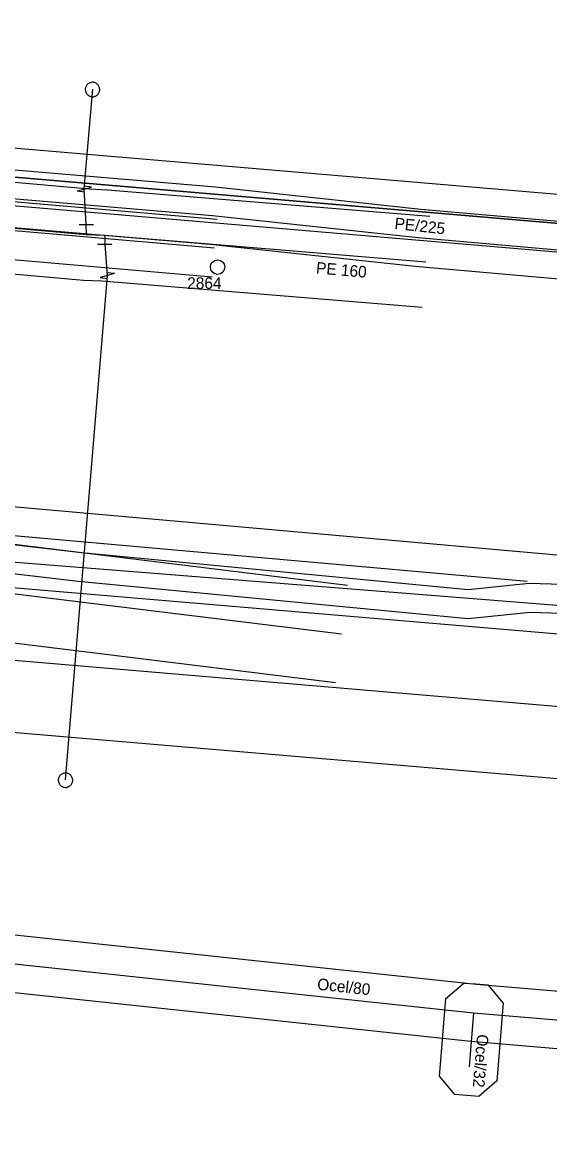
# Model space of a CAD drawing. Extents: x -762993 to -761845, y -975230 to -974501.
# Drawn here: x -762178.08 to -762159.81, y -975032.89 to -974994.1 of the extents above; entities that cross this region are included whole.
import ezdxf

# ---------------------------------------------------------------- set-up
doc = ezdxf.new("R2010")
doc.units = 0
for name, color, linetype in [('IS_CETIN_OP', 7, 'Continuous'), ('IS_CETIN_podzem metalika zam', 7, 'Continuous'), ('IS_CETIN_podzem optika zam', 7, 'Continuous'), ('IS_CETIN_podzem out of order', 7, 'Continuous'), ('IS_CEZ-T_parovod', 7, 'Continuous'), ('IS_CEZ-T_parovod OP', 7, 'Continuous'), ('IS_CRA_podzem telekomunikace', 7, 'Continuous'), ('IS_DPmUL_OP', 7, 'Continuous'), ('IS_DPmUL_trakce anotace', 7, 'Continuous'), ('IS_DPmUL_trakce stozary', 7, 'Continuous'), ('IS_DPmUL_VO vedeni podzem', 7, 'Continuous'), ('IS_GASNET_plyn NTL anotace', 7, 'Continuous'), ('IS_GASNET_plyn NTL pripojky', 7, 'Continuous'), ('IS_GASNET_plyn NTL rad', 7, 'Continuous'), ('IS_GASNET_plyn OP', 7, 'Continuous'), ('IS_SCVK_kanalizace jednotna', 7, 'Continuous'), ('IS_SCVK_kanalizace OP', 7, 'Continuous'), ('IS_SCVK_vodovod anotace', 7, 'Continuous'), ('IS_SCVK_vodovod OP', 7, 'Continuous'), ('IS_SCVK_vodovod pripojky', 7, 'Continuous'), ('IS_SCVK_vodovod privadec', 7, 'Continuous'), ('IS_SCVK_vodovod znaky', 7, 'Continuous')]:
    doc.layers.add(name, color=color, linetype=linetype)

msp = doc.modelspace()

# ---------------------------------------------------------------- linework, layer by layer
at = {"layer": 'IS_CETIN_OP'}
msp.add_line((-762187.135, -975010.105), (-762159.034, -975012.594), dxfattribs=at)
for points in [[(-762217.822, -974995.035), (-762216.005, -974995.184), (-762184.57, -974998.003), (-762178.542, -974998.433), (-762152.471, -975000.654), (-762131.203, -975002.624), (-762124.809, -975003.153), (-762118.93, -975003.623), (-762113.193, -975004.083), (-762107.364, -975004.514), (-762100.398, -975005.204), (-762087.589, -975006.295)], [(-762217.984, -974997.029), (-762216.175, -974997.176), (-762184.73, -974999.997), (-762178.698, -975000.427), (-762152.649, -975002.646), (-762131.377, -975004.616), (-762124.971, -975005.147), (-762119.09, -975005.617), (-762113.347, -975006.077), (-762107.536, -975006.506), (-762100.582, -975007.196), (-762087.759, -975008.287)], [(-762105.752, -975019.119), (-762108.956, -975019.272), (-762116.886, -975018.639), (-762118.209, -975018.27), (-762121.344, -975018.26), (-762126.32, -975017.734), (-762130.385, -975017.267), (-762131.367, -975016.856), (-762135.732, -975016.981), (-762156.063, -975015.079), (-762157.972, -975014.627), (-762160.485, -975014.551), (-762162.638, -975014.765), (-762176.145, -975013.475), (-762180.887, -975012.925), (-762183.621, -975012.711), (-762185.704, -975012.236), (-762187.743, -975012.352), (-762193.286, -975011.893), (-762194.38, -975011.419), (-762195.086, -975011.619)]]:
    msp.add_lwpolyline(points, dxfattribs=at)
at = {"layer": 'IS_CETIN_podzem metalika zam'}
msp.add_lwpolyline([(-762105.8, -975018.12), (-762108.94, -975018.27), (-762116.71, -975017.65), (-762118.07, -975017.27), (-762121.29, -975017.26), (-762126.21, -975016.74), (-762130.13, -975016.29), (-762131.18, -975015.85), (-762135.7, -975015.98), (-762155.9, -975014.09), (-762157.84, -975013.63), (-762160.52, -975013.55), (-762162.64, -975013.76), (-762176.04, -975012.48), (-762180.79, -975011.93), (-762183.47, -975011.72), (-762185.62, -975011.23), (-762187.73, -975011.35), (-762193.04, -975010.91), (-762194.31, -975010.36), (-762195.97, -975010.83)], dxfattribs=at)
at = {"layer": 'IS_CETIN_podzem optika zam'}
for points in [[(-762217.903, -974996.032), (-762216.09, -974996.18), (-762184.65, -974999), (-762178.62, -974999.43), (-762152.56, -975001.65), (-762131.29, -975003.62), (-762124.89, -975004.15), (-762119.01, -975004.62), (-762113.27, -975005.08), (-762107.45, -975005.51), (-762100.49, -975006.2), (-762087.674, -975007.291)], [(-762187.23, -975011.1), (-762160.59, -975013.46)]]:
    msp.add_lwpolyline(points, dxfattribs=at)
at = {"layer": 'IS_CETIN_podzem out of order'}
msp.add_lwpolyline([(-762250.2, -975005.66), (-762210.15, -975010), (-762201.16, -975010.99), (-762121.16, -975017.35), (-762071.23, -975020.85), (-762043.47, -975023.41)], dxfattribs=at)
at = {"layer": 'IS_CEZ-T_parovod'}
msp.add_lwpolyline([(-761997.94, -975128.34), (-762040.63, -975080.79), (-762092.91, -975023.16), (-762093.78, -975023), (-762095.1, -975022.88), (-762139.5, -975019.26), (-762139.25, -975015.36), (-762142, -975015.09), (-762142.45, -975019.26), (-762189.8, -975015.24), (-762189.54, -975011.07), (-762194.02, -975010.75), (-762194.39, -975014.25), (-762239.28, -975010.18), (-762239.14, -975006.45), (-762242.94, -975006.24), (-762243.22, -975009.53), (-762252.6, -975008.69), (-762274.12, -975007.08), (-762277.86, -975004.82)], dxfattribs=at)
at = {"layer": 'IS_CEZ-T_parovod OP'}
for points in [[(-761996.08, -975126.67), (-762038.774, -975079.115), (-762091.626, -975020.854), (-762093.44, -975020.521), (-762094.885, -975020.389), (-762136.848, -975016.968), (-762136.601, -975013.108), (-762144.22, -975012.36), (-762144.673, -975016.562), (-762187.153, -975012.956), (-762186.891, -975008.753), (-762196.252, -975008.084), (-762196.617, -975011.538), (-762236.693, -975007.904), (-762236.55, -975004.089), (-762245.225, -975003.61), (-762245.498, -975006.816), (-762252.395, -975006.198), (-762273.338, -975004.632), (-762275.663, -975003.227)], [(-761999.8, -975130.01), (-762042.486, -975082.465), (-762094.187, -975025.473), (-762095.315, -975025.371), (-762140.2, -975021.711), (-762140.227, -975021.958), (-762192.447, -975017.524), (-762192.411, -975016.94), (-762241.867, -975012.456), (-762241.856, -975012.162), (-762252.805, -975011.182), (-762274.902, -975009.528), (-762278.275, -975007.49)]]:
    msp.add_lwpolyline(points, dxfattribs=at)
at = {"layer": 'IS_CRA_podzem telekomunikace'}
msp.add_lwpolyline([(-762257.583, -974994.102), (-762251.601, -974995.42), (-762242.483, -974996.496), (-762240.634, -974996.224), (-762237.225, -974994.464), (-762216.085, -974996.188), (-762184.646, -974998.998), (-762178.626, -974999.438), (-762152.565, -975001.658), (-762131.295, -975003.618), (-762124.896, -975004.158), (-762119.016, -975004.628), (-762113.267, -975005.088), (-762107.455, -975005.508), (-762100.504, -975006.198), (-762086.855, -975007.364)], dxfattribs=at)
at = {"layer": 'IS_DPmUL_OP'}
msp.add_line((-762171.511, -975002.926), (-762197.933, -975000.64), dxfattribs=at)
msp.add_lwpolyline([(-762171.339, -975000.934), (-762197.755, -974998.648)], dxfattribs=at)
at = {"layer": 'IS_DPmUL_trakce stozary'}
msp.add_circle((-762171.318, -975002.583), 0.25, dxfattribs=at)
at = {"layer": 'IS_DPmUL_VO vedeni podzem'}
msp.add_lwpolyline([(-762171.425, -975001.93), (-762197.841, -974999.644)], dxfattribs=at)
at = {"layer": 'IS_GASNET_plyn NTL pripojky'}
msp.add_lwpolyline([(-762162.45, -975028.42), (-762162.6, -975030.29)], dxfattribs=at)
at = {"layer": 'IS_GASNET_plyn NTL rad'}
for points in [[(-762152.06, -975002.65), (-762164.37, -975001.57), (-762171.49, -975000.8), (-762180.35, -975000.05), (-762191.928, -974999.15), (-762192.87, -974999.06), (-762193.62, -974998.98), (-762196.019, -974998.86), (-762209.34, -974997.53), (-762211.92, -974997.29), (-762211.926, -974997.289), (-762215.99, -974996.98), (-762229.04, -974995.92), (-762230.6, -974995.81), (-762231.15, -974995.79), (-762234.191, -974995.47), (-762234.57, -974995.47)], [(-762200.13, -975024.62), (-762197.953, -975024.87), (-762195.07, -975025.2), (-762193.3, -975025.13), (-762162.45, -975028.42), (-762149.72, -975029.5), (-762136.08, -975030.63)]]:
    msp.add_lwpolyline(points, dxfattribs=at)
at = {"layer": 'IS_GASNET_plyn OP'}
for points in [[(-762215.912, -974995.983), (-762211.806, -974996.295), (-762211.795, -974996.297), (-762209.244, -974996.535), (-762195.944, -974997.862), (-762193.542, -974997.983), (-762192.769, -974998.065), (-762191.842, -974998.154), (-762180.269, -974999.053), (-762171.394, -974999.805), (-762164.273, -975000.575), (-762151.966, -975001.654)], [(-762152.154, -975003.646), (-762164.467, -975002.565), (-762171.586, -975001.795), (-762180.431, -975001.047), (-762192.014, -975000.146), (-762192.971, -975000.055), (-762193.698, -974999.977), (-762196.094, -974999.858), (-762209.436, -974998.525), (-762212.002, -974998.286), (-762212.024, -974998.284), (-762212.049, -974998.282), (-762216.068, -974997.977)]]:
    msp.add_lwpolyline(points, dxfattribs=at)
for points in [[(-762200.428, -975023.58), (-762200.016, -975023.627), (-762195.033, -975024.198), (-762193.267, -975024.128), (-762162.355, -975027.424), (-762149.636, -975028.503), (-762135.997, -975029.633), (-762135.584, -975029.667), (-762135.049, -975030.3), (-762135.083, -975030.713), (-762135.117, -975031.126), (-762135.75, -975031.661), (-762136.163, -975031.627), (-762149.804, -975030.497), (-762162.545, -975029.416), (-762193.333, -975026.132), (-762195.107, -975026.202), (-762200.244, -975025.613), (-762200.655, -975025.566), (-762201.17, -975024.918), (-762201.123, -975024.506), (-762201.076, -975024.095)], [(-762161.42, -975028.087), (-762161.453, -975028.5), (-762161.603, -975030.37), (-762161.636, -975030.783), (-762162.267, -975031.32), (-762162.68, -975031.287), (-762163.093, -975031.254), (-762163.63, -975030.623), (-762163.597, -975030.21), (-762163.447, -975028.34), (-762163.414, -975027.927), (-762162.783, -975027.39), (-762162.37, -975027.423), (-762161.957, -975027.456)]]:
    msp.add_lwpolyline(points, close=True, dxfattribs=at)
at = {"layer": 'IS_SCVK_kanalizace jednotna'}
msp.add_lwpolyline([(-762195.393, -975011.808), (-762167.023, -975015.287)], dxfattribs=at)
at = {"layer": 'IS_SCVK_kanalizace OP'}
for p, q in [((-762195.236, -975010.115), (-762166.816, -975013.6)), ((-762195.55, -975013.501), (-762167.23, -975016.974))]:
    msp.add_line(p, q, dxfattribs=at)
at = {"layer": 'IS_SCVK_vodovod OP'}
for points in [[(-762202.898, -974997.152), (-762199.388, -974997.773), (-762175.758, -974999.875), (-762175.129, -974999.903), (-762163.968, -975000.821)], [(-762201.291, -975000.645), (-762199.804, -975000.909), (-762175.968, -975003.029), (-762175.329, -975003.057), (-762164.228, -975003.971)]]:
    msp.add_lwpolyline(points, dxfattribs=at)
at = {"layer": 'IS_SCVK_vodovod pripojky'}
for points in [[(-762175.939, -974999.873), (-762175.642, -974996.418)], [(-762175.87, -975001.106), (-762175.939, -974999.873)], [(-762175.228, -975001.8), (-762175.141, -975002.876)], [(-762175.141, -975002.876), (-762176.6, -975020.349)]]:
    msp.add_lwpolyline(points, dxfattribs=at)
at = {"layer": 'IS_SCVK_vodovod privadec'}
msp.add_lwpolyline([(-762202.357, -974998.852), (-762199.596, -974999.341), (-762175.863, -975001.452), (-762175.229, -975001.48), (-762164.098, -975002.396)], dxfattribs=at)
at = {"layer": 'IS_SCVK_vodovod znaky'}
for points in [[(-762175.904, -974996.409), (-762175.905, -974996.435)], [(-762175.904, -974996.409), (-762175.905, -974996.435)], [(-762175.905, -974996.435), (-762175.902, -974996.461)], [(-762175.905, -974996.435), (-762175.902, -974996.461)], [(-762175.9, -974996.383), (-762175.904, -974996.409)], [(-762175.9, -974996.383), (-762175.904, -974996.409)], [(-762175.902, -974996.461), (-762175.898, -974996.487)], [(-762175.902, -974996.461), (-762175.898, -974996.487)], [(-762175.894, -974996.357), (-762175.9, -974996.383)], [(-762175.894, -974996.357), (-762175.9, -974996.383)], [(-762175.898, -974996.487), (-762175.89, -974996.512)], [(-762175.898, -974996.487), (-762175.89, -974996.512)], [(-762175.885, -974996.333), (-762175.894, -974996.357)], [(-762175.885, -974996.333), (-762175.894, -974996.357)], [(-762175.89, -974996.512), (-762175.88, -974996.535)], [(-762175.89, -974996.512), (-762175.88, -974996.535)], [(-762175.874, -974996.309), (-762175.885, -974996.333)], [(-762175.874, -974996.309), (-762175.885, -974996.333)], [(-762175.861, -974996.287), (-762175.874, -974996.309)], [(-762175.861, -974996.287), (-762175.874, -974996.309)], [(-762175.845, -974996.266), (-762175.861, -974996.287)], [(-762175.845, -974996.266), (-762175.861, -974996.287)], [(-762175.827, -974996.247), (-762175.845, -974996.266)], [(-762175.827, -974996.247), (-762175.845, -974996.266)], [(-762175.807, -974996.23), (-762175.827, -974996.247)], [(-762175.807, -974996.23), (-762175.827, -974996.247)], [(-762175.785, -974996.216), (-762175.807, -974996.23)], [(-762175.785, -974996.216), (-762175.807, -974996.23)], [(-762175.762, -974996.202), (-762175.785, -974996.216)], [(-762175.762, -974996.202), (-762175.785, -974996.216)], [(-762175.738, -974996.192), (-762175.762, -974996.202)], [(-762175.738, -974996.192), (-762175.762, -974996.202)], [(-762175.713, -974996.185), (-762175.738, -974996.192)], [(-762175.713, -974996.185), (-762175.738, -974996.192)], [(-762175.687, -974996.18), (-762175.713, -974996.185)], [(-762175.687, -974996.18), (-762175.713, -974996.185)], [(-762175.662, -974996.179), (-762175.687, -974996.18)], [(-762175.662, -974996.179), (-762175.687, -974996.18)], [(-762175.635, -974996.179), (-762175.662, -974996.179)], [(-762175.635, -974996.179), (-762175.662, -974996.179)], [(-762175.609, -974996.182), (-762175.635, -974996.179)], [(-762175.609, -974996.182), (-762175.635, -974996.179)], [(-762175.584, -974996.189), (-762175.609, -974996.182)], [(-762175.584, -974996.189), (-762175.609, -974996.182)], [(-762175.559, -974996.197), (-762175.584, -974996.189)], [(-762175.559, -974996.197), (-762175.584, -974996.189)], [(-762175.535, -974996.208), (-762175.559, -974996.197)], [(-762175.535, -974996.208), (-762175.559, -974996.197)], [(-762175.513, -974996.223), (-762175.535, -974996.208)], [(-762175.513, -974996.223), (-762175.535, -974996.208)], [(-762175.492, -974996.238), (-762175.513, -974996.223)], [(-762175.492, -974996.238), (-762175.513, -974996.223)], [(-762175.473, -974996.257), (-762175.492, -974996.238)], [(-762175.473, -974996.257), (-762175.492, -974996.238)], [(-762175.457, -974996.276), (-762175.473, -974996.257)], [(-762175.457, -974996.276), (-762175.473, -974996.257)], [(-762175.442, -974996.298), (-762175.457, -974996.276)], [(-762175.442, -974996.298), (-762175.457, -974996.276)], [(-762175.429, -974996.321), (-762175.442, -974996.298)], [(-762175.429, -974996.321), (-762175.442, -974996.298)], [(-762175.435, -974996.547), (-762175.424, -974996.524)], [(-762175.435, -974996.547), (-762175.424, -974996.524)], [(-762175.419, -974996.345), (-762175.429, -974996.321)], [(-762175.419, -974996.345), (-762175.429, -974996.321)], [(-762175.424, -974996.524), (-762175.415, -974996.499)], [(-762175.424, -974996.524), (-762175.415, -974996.499)], [(-762175.412, -974996.37), (-762175.419, -974996.345)], [(-762175.412, -974996.37), (-762175.419, -974996.345)], [(-762175.415, -974996.499), (-762175.409, -974996.474)], [(-762175.415, -974996.499), (-762175.409, -974996.474)], [(-762175.407, -974996.395), (-762175.412, -974996.37)], [(-762175.407, -974996.395), (-762175.412, -974996.37)], [(-762175.409, -974996.474), (-762175.405, -974996.448)], [(-762175.409, -974996.474), (-762175.405, -974996.448)], [(-762175.404, -974996.422), (-762175.407, -974996.395)], [(-762175.404, -974996.422), (-762175.407, -974996.395)], [(-762175.405, -974996.448), (-762175.404, -974996.422)], [(-762175.405, -974996.448), (-762175.404, -974996.422)], [(-762175.88, -974996.535), (-762175.868, -974996.559)], [(-762175.88, -974996.535), (-762175.868, -974996.559)], [(-762175.868, -974996.559), (-762175.853, -974996.58)], [(-762175.868, -974996.559), (-762175.853, -974996.58)], [(-762175.853, -974996.58), (-762175.836, -974996.601)], [(-762175.853, -974996.58), (-762175.836, -974996.601)], [(-762175.836, -974996.601), (-762175.817, -974996.618)], [(-762175.836, -974996.601), (-762175.817, -974996.618)], [(-762175.817, -974996.618), (-762175.797, -974996.634)], [(-762175.817, -974996.618), (-762175.797, -974996.634)], [(-762175.797, -974996.634), (-762175.774, -974996.648)], [(-762175.797, -974996.634), (-762175.774, -974996.648)], [(-762175.774, -974996.648), (-762175.751, -974996.659)], [(-762175.774, -974996.648), (-762175.751, -974996.659)], [(-762175.751, -974996.659), (-762175.725, -974996.668)], [(-762175.751, -974996.659), (-762175.725, -974996.668)], [(-762175.725, -974996.668), (-762175.7, -974996.674)], [(-762175.725, -974996.668), (-762175.7, -974996.674)], [(-762175.7, -974996.674), (-762175.674, -974996.677)], [(-762175.7, -974996.674), (-762175.674, -974996.677)], [(-762175.674, -974996.677), (-762175.648, -974996.677)], [(-762175.674, -974996.677), (-762175.648, -974996.677)], [(-762175.648, -974996.677), (-762175.622, -974996.676)], [(-762175.648, -974996.677), (-762175.622, -974996.676)], [(-762175.622, -974996.676), (-762175.596, -974996.671)], [(-762175.622, -974996.676), (-762175.596, -974996.671)], [(-762175.596, -974996.671), (-762175.571, -974996.664)], [(-762175.596, -974996.671), (-762175.571, -974996.664)], [(-762175.571, -974996.664), (-762175.547, -974996.654)], [(-762175.571, -974996.664), (-762175.547, -974996.654)], [(-762175.547, -974996.654), (-762175.524, -974996.642)], [(-762175.547, -974996.654), (-762175.524, -974996.642)], [(-762175.524, -974996.642), (-762175.503, -974996.626)], [(-762175.524, -974996.642), (-762175.503, -974996.626)], [(-762175.503, -974996.626), (-762175.483, -974996.61)], [(-762175.503, -974996.626), (-762175.483, -974996.61)], [(-762175.483, -974996.61), (-762175.465, -974996.591)], [(-762175.483, -974996.61), (-762175.465, -974996.591)], [(-762175.465, -974996.591), (-762175.448, -974996.57)], [(-762175.465, -974996.591), (-762175.448, -974996.57)], [(-762175.448, -974996.57), (-762175.435, -974996.547)], [(-762175.448, -974996.57), (-762175.435, -974996.547)], [(-762176.186, -974999.936), (-762175.692, -974999.81)], [(-762176.186, -974999.936), (-762175.933, -974999.973)], [(-762175.692, -974999.81), (-762175.944, -974999.773)], [(-762176.12, -975001.111), (-762175.62, -975001.101)], [(-762175.863, -975001.452), (-762175.87, -975001.106)], [(-762175.229, -975001.48), (-762175.228, -975001.8)], [(-762174.978, -975001.798), (-762175.478, -975001.801)], [(-762174.895, -975002.807), (-762175.386, -975002.945)], [(-762175.386, -975002.945), (-762175.133, -975002.976)], [(-762174.895, -975002.807), (-762175.149, -975002.775)], [(-762176.763, -975020.182), (-762176.781, -975020.201)], [(-762176.763, -975020.182), (-762176.781, -975020.201)], [(-762176.743, -975020.165), (-762176.763, -975020.182)], [(-762176.743, -975020.165), (-762176.763, -975020.182)], [(-762176.722, -975020.15), (-762176.743, -975020.165)], [(-762176.722, -975020.15), (-762176.743, -975020.165)], [(-762176.699, -975020.137), (-762176.722, -975020.15)], [(-762176.699, -975020.137), (-762176.722, -975020.15)], [(-762176.675, -975020.127), (-762176.699, -975020.137)], [(-762176.675, -975020.127), (-762176.699, -975020.137)], [(-762176.65, -975020.119), (-762176.675, -975020.127)], [(-762176.65, -975020.119), (-762176.675, -975020.127)], [(-762176.625, -975020.114), (-762176.65, -975020.119)], [(-762176.625, -975020.114), (-762176.65, -975020.119)], [(-762176.599, -975020.111), (-762176.625, -975020.114)], [(-762176.599, -975020.111), (-762176.625, -975020.114)], [(-762176.572, -975020.111), (-762176.599, -975020.111)], [(-762176.572, -975020.111), (-762176.599, -975020.111)], [(-762176.546, -975020.116), (-762176.572, -975020.111)], [(-762176.546, -975020.116), (-762176.572, -975020.111)], [(-762176.521, -975020.122), (-762176.546, -975020.116)], [(-762176.521, -975020.122), (-762176.546, -975020.116)], [(-762176.496, -975020.13), (-762176.521, -975020.122)], [(-762176.496, -975020.13), (-762176.521, -975020.122)], [(-762176.473, -975020.141), (-762176.496, -975020.13)], [(-762176.473, -975020.141), (-762176.496, -975020.13)], [(-762176.45, -975020.154), (-762176.473, -975020.141)], [(-762176.45, -975020.154), (-762176.473, -975020.141)], [(-762176.429, -975020.17), (-762176.45, -975020.154)], [(-762176.429, -975020.17), (-762176.45, -975020.154)], [(-762176.41, -975020.188), (-762176.429, -975020.17)], [(-762176.41, -975020.188), (-762176.429, -975020.17)], [(-762176.836, -975020.318), (-762176.839, -975020.344)], [(-762176.836, -975020.318), (-762176.839, -975020.344)], [(-762176.839, -975020.344), (-762176.839, -975020.371)], [(-762176.839, -975020.344), (-762176.839, -975020.371)], [(-762176.839, -975020.371), (-762176.837, -975020.396)], [(-762176.839, -975020.371), (-762176.837, -975020.396)], [(-762176.837, -975020.396), (-762176.832, -975020.423)], [(-762176.837, -975020.396), (-762176.832, -975020.423)], [(-762176.83, -975020.293), (-762176.836, -975020.318)], [(-762176.83, -975020.293), (-762176.836, -975020.318)], [(-762176.832, -975020.423), (-762176.824, -975020.447)], [(-762176.832, -975020.423), (-762176.824, -975020.447)], [(-762176.822, -975020.269), (-762176.83, -975020.293)], [(-762176.822, -975020.269), (-762176.83, -975020.293)], [(-762176.824, -975020.447), (-762176.814, -975020.471)], [(-762176.824, -975020.447), (-762176.814, -975020.471)], [(-762176.811, -975020.244), (-762176.822, -975020.269)], [(-762176.811, -975020.244), (-762176.822, -975020.269)], [(-762176.814, -975020.471), (-762176.801, -975020.494)], [(-762176.814, -975020.471), (-762176.801, -975020.494)], [(-762176.797, -975020.222), (-762176.811, -975020.244)], [(-762176.797, -975020.222), (-762176.811, -975020.244)], [(-762176.801, -975020.494), (-762176.786, -975020.516)], [(-762176.801, -975020.494), (-762176.786, -975020.516)], [(-762176.781, -975020.201), (-762176.797, -975020.222)], [(-762176.781, -975020.201), (-762176.797, -975020.222)], [(-762176.786, -975020.516), (-762176.769, -975020.535)], [(-762176.786, -975020.516), (-762176.769, -975020.535)], [(-762176.769, -975020.535), (-762176.75, -975020.554)], [(-762176.769, -975020.535), (-762176.75, -975020.554)], [(-762176.75, -975020.554), (-762176.729, -975020.569)], [(-762176.75, -975020.554), (-762176.729, -975020.569)], [(-762176.729, -975020.569), (-762176.706, -975020.582)], [(-762176.729, -975020.569), (-762176.706, -975020.582)], [(-762176.48, -975020.586), (-762176.457, -975020.573)], [(-762176.48, -975020.586), (-762176.457, -975020.573)], [(-762176.457, -975020.573), (-762176.435, -975020.558)], [(-762176.457, -975020.573), (-762176.435, -975020.558)], [(-762176.435, -975020.558), (-762176.415, -975020.541)], [(-762176.435, -975020.558), (-762176.415, -975020.541)], [(-762176.415, -975020.541), (-762176.398, -975020.522)], [(-762176.415, -975020.541), (-762176.398, -975020.522)], [(-762176.393, -975020.208), (-762176.41, -975020.188)], [(-762176.393, -975020.208), (-762176.41, -975020.188)], [(-762176.398, -975020.522), (-762176.382, -975020.501)], [(-762176.398, -975020.522), (-762176.382, -975020.501)], [(-762176.377, -975020.229), (-762176.393, -975020.208)], [(-762176.377, -975020.229), (-762176.393, -975020.208)], [(-762176.382, -975020.501), (-762176.368, -975020.478)], [(-762176.382, -975020.501), (-762176.368, -975020.478)], [(-762176.365, -975020.251), (-762176.377, -975020.229)], [(-762176.365, -975020.251), (-762176.377, -975020.229)], [(-762176.368, -975020.478), (-762176.357, -975020.455)], [(-762176.368, -975020.478), (-762176.357, -975020.455)], [(-762176.355, -975020.275), (-762176.365, -975020.251)], [(-762176.355, -975020.275), (-762176.365, -975020.251)], [(-762176.357, -975020.455), (-762176.349, -975020.43)], [(-762176.357, -975020.455), (-762176.349, -975020.43)], [(-762176.347, -975020.301), (-762176.355, -975020.275)], [(-762176.347, -975020.301), (-762176.355, -975020.275)], [(-762176.349, -975020.43), (-762176.344, -975020.405)], [(-762176.349, -975020.43), (-762176.344, -975020.405)], [(-762176.342, -975020.327), (-762176.347, -975020.301)], [(-762176.342, -975020.327), (-762176.347, -975020.301)], [(-762176.344, -975020.405), (-762176.34, -975020.378)], [(-762176.344, -975020.405), (-762176.34, -975020.378)], [(-762176.34, -975020.353), (-762176.342, -975020.327)], [(-762176.34, -975020.353), (-762176.342, -975020.327)], [(-762176.34, -975020.378), (-762176.34, -975020.353)], [(-762176.34, -975020.378), (-762176.34, -975020.353)], [(-762176.706, -975020.582), (-762176.683, -975020.593)], [(-762176.706, -975020.582), (-762176.683, -975020.593)], [(-762176.683, -975020.593), (-762176.658, -975020.601)], [(-762176.683, -975020.593), (-762176.658, -975020.601)], [(-762176.658, -975020.601), (-762176.632, -975020.607)], [(-762176.658, -975020.601), (-762176.632, -975020.607)], [(-762176.632, -975020.607), (-762176.606, -975020.611)], [(-762176.632, -975020.607), (-762176.606, -975020.611)], [(-762176.606, -975020.611), (-762176.581, -975020.611)], [(-762176.606, -975020.611), (-762176.581, -975020.611)], [(-762176.581, -975020.611), (-762176.554, -975020.609)], [(-762176.581, -975020.611), (-762176.554, -975020.609)], [(-762176.554, -975020.609), (-762176.528, -975020.604)], [(-762176.554, -975020.609), (-762176.528, -975020.604)], [(-762176.528, -975020.604), (-762176.503, -975020.596)], [(-762176.528, -975020.604), (-762176.503, -975020.596)], [(-762176.503, -975020.596), (-762176.48, -975020.586)], [(-762176.503, -975020.596), (-762176.48, -975020.586)]]:
    msp.add_lwpolyline(points, dxfattribs=at)

# ---------------------------------------------------------------- texts
at = {"layer": 'IS_DPmUL_trakce anotace'}
msp.add_text('2864', height=0.4, dxfattribs=at).set_placement((-762172.372, -975003.336))
at = {"layer": 'IS_GASNET_plyn NTL anotace'}
for s, rotation, p in [('PE/225', 353.8277, (-762165.201, -975001.259)), ('Ocel/80', 353.9127, (-762167.882, -975027.619)), ('Ocel/32', 265.4139, (-762162.325, -975029.155))]:
    msp.add_text(s, height=0.4, rotation=rotation, dxfattribs=at).set_placement(p)
at = {"layer": 'IS_SCVK_vodovod anotace'}
msp.add_text('PE 160', height=0.4, rotation=355, dxfattribs=at).set_placement((-762167.918, -975002.8))

doc.saveas('drawing.dxf')
